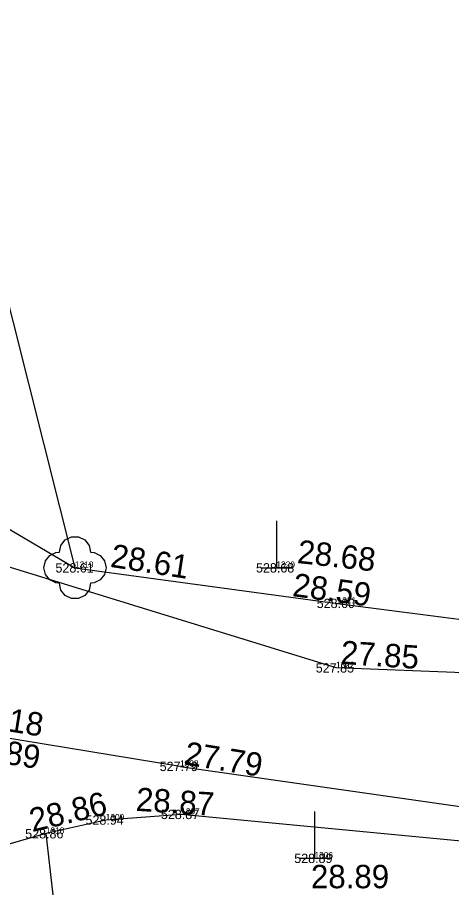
# Model space of a CAD drawing. Extents: x -866693 to -866303, y -1041966 to -1040244.
# Drawn here: x -866474.26 to -866460.32, y -1041765.62 to -1041737.67 of the extents above; entities that cross this region are included whole.
import ezdxf

# ---------------------------------------------------------------- set-up
doc = ezdxf.new("R2010")
doc.units = 0
for name, color, linetype in [('12 potok _kanál-břeh', 7, 'Continuous'), ('13 potok _kanál-dno', 7, 'Continuous'), ('41 tyčový znak _informační tabule', 7, 'Continuous'), ('60 strom bez rozlišení', 7, 'Continuous'), ('7 hrana svah nahoře', 7, 'Continuous'), ('8 hrana svah dole', 7, 'Continuous'), ('Bod', 7, 'Continuous'), ('Nadmořská výška', 7, 'Continuous'), ('Nadmořská výška_tisk', 7, 'Continuous'), ('Číslo bodu', 7, 'Continuous')]:
    doc.layers.add(name, color=color, linetype=linetype)

msp = doc.modelspace()

# ---------------------------------------------------------------- linework, layer by layer
at = {"layer": '12 potok _kanál-břeh'}
for p, q in [((-866475.529, -1041753.503), (-866472.409, -1041755.326)), ((-866472.409, -1041755.326), (-866463.982, -1041756.472)), ((-866463.982, -1041756.472), (-866453.489, -1041757.844)), ((-866469.001, -1041763.241), (-866471.422, -1041763.424)), ((-866453.486, -1041764.725), (-866469.001, -1041763.241)), ((-866471.422, -1041763.424), (-866473.345, -1041763.857)), ((-866473.345, -1041763.857), (-866475.673, -1041764.528))]:
    msp.add_line(p, q, dxfattribs=at)
at = {"layer": '13 potok _kanál-dno'}
for p, q in [((-866464.03, -1041758.542), (-866477.086, -1041754.517)), ((-866452.757, -1041758.973), (-866464.03, -1041758.542)), ((-866469.037, -1041761.703), (-866476.29, -1041760.51)), ((-866469.037, -1041761.703), (-866453.338, -1041763.941))]:
    msp.add_line(p, q, dxfattribs=at)
at = {"layer": '41 tyčový znak _informační tabule'}
for points in [[(-866465.944, -1041753.825), (-866465.944, -1041755.325)], [(-866466.444, -1041755.325), (-866465.444, -1041755.325)], [(-866464.72, -1041763.146), (-866464.72, -1041764.646)], [(-866465.22, -1041764.646), (-866464.22, -1041764.646)]]:
    msp.add_lwpolyline(points, dxfattribs=at)
at = {"layer": '60 strom bez rozlišení'}
msp.add_lwpolyline([(-866471.409, -1041755.326), (-866471.459, -1041755.543), (-866471.598, -1041755.717), (-866471.798, -1041755.814), (-866471.909, -1041755.826), (-866471.959, -1041756.043), (-866472.098, -1041756.217), (-866472.298, -1041756.314), (-866472.52, -1041756.314), (-866472.721, -1041756.217), (-866472.86, -1041756.043), (-866472.909, -1041755.826), (-866473.02, -1041755.814), (-866473.221, -1041755.717), (-866473.36, -1041755.543), (-866473.409, -1041755.326), (-866473.36, -1041755.109), (-866473.221, -1041754.935), (-866473.02, -1041754.839), (-866472.909, -1041754.826), (-866472.86, -1041754.609), (-866472.721, -1041754.435), (-866472.52, -1041754.339), (-866472.298, -1041754.339), (-866472.098, -1041754.435), (-866471.959, -1041754.609), (-866471.909, -1041754.826), (-866471.798, -1041754.839), (-866471.598, -1041754.935), (-866471.459, -1041755.109)], close=True, dxfattribs=at)
msp.add_lwpolyline([(-866472.434, -1041755.326), (-866472.409, -1041755.326), (-866472.384, -1041755.326)], dxfattribs=at)
at = {"layer": '7 hrana svah nahoře'}
msp.add_line((-866476.87, -1041737.672), (-866472.409, -1041755.326), dxfattribs=at)
at = {"layer": '8 hrana svah dole'}
msp.add_line((-866473.345, -1041763.857), (-866473.125, -1041765.823), dxfattribs=at)
at = {"layer": 'Bod'}
for p, q in [((-866472.409, -1041755.326), (-866472.409, -1041755.326)), ((-866465.944, -1041755.325), (-866465.944, -1041755.325)), ((-866463.982, -1041756.472), (-866463.982, -1041756.472)), ((-866464.03, -1041758.542), (-866464.03, -1041758.542)), ((-866469.037, -1041761.703), (-866469.037, -1041761.703)), ((-866469.001, -1041763.241), (-866469.001, -1041763.241)), ((-866471.422, -1041763.424), (-866471.422, -1041763.424)), ((-866473.345, -1041763.857), (-866473.345, -1041763.857)), ((-866464.72, -1041764.646), (-866464.72, -1041764.646))]:
    msp.add_line(p, q, dxfattribs=at)

# ---------------------------------------------------------------- texts
at = {"layer": 'Nadmořská výška'}
for s, p in [('528.61', (-866473.035, -1041755.48)), ('528.68', (-866466.598, -1041755.48)), ('528.60', (-866464.65, -1041756.62)), ('527.85', (-866464.68, -1041758.69)), ('527.79', (-866469.691, -1041761.85)), ('528.87', (-866469.65, -1041763.39)), ('528.94', (-866472.071, -1041763.57)), ('528.86', (-866474.008, -1041764.01)), ('528.89', (-866465.371, -1041764.8))]:
    msp.add_text(s, height=0.3, dxfattribs=at).set_placement(p)
at = {"layer": 'Nadmořská výška_tisk'}
for s, rotation, p in [('28.68', 353.7388, (-866465.298, -1041755.173)), ('28.61', 351.1239, (-866471.3, -1041755.296)), ('28.59', 352.2747, (-866465.453, -1041756.236)), ('27.85', 356.2544, (-866463.897, -1041758.411)), ('29.18', 350.952, (-866475.967, -1041760.351)), ('27.89', 350.8885, (-866476.068, -1041761.389)), ('27.79', 350.8241, (-866468.934, -1041761.635)), ('28.86', 13.3925, (-866473.769, -1041763.805)), ('28.87', 356.2899, (-866470.47, -1041763.123))]:
    msp.add_text(s, height=0.75, rotation=rotation, dxfattribs=at).set_placement(p)
msp.add_text('28.89', height=0.75, dxfattribs=at).set_placement((-866464.835, -1041765.608))
at = {"layer": 'Číslo bodu'}
for s, p in [('1319', (-866472.409, -1041755.326)), ('1320', (-866465.944, -1041755.325)), ('1321', (-866463.982, -1041756.472)), ('1322', (-866464.03, -1041758.542)), ('1308', (-866469.037, -1041761.703)), ('1307', (-866469.001, -1041763.241)), ('1309', (-866471.422, -1041763.424)), ('1310', (-866473.345, -1041763.857)), ('1306', (-866464.72, -1041764.646))]:
    msp.add_text(s, height=0.2, dxfattribs=at).set_placement(p)

doc.saveas('drawing.dxf')
